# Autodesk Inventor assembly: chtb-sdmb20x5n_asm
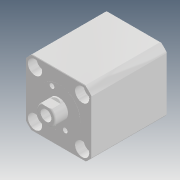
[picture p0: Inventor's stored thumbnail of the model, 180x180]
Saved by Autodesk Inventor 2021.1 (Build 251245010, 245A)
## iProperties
Company: Microsoft
Created: 2018-05
Part Number: chtb-sdmb20x5n_asm
Description: STEP AP214
Document SubType Name: Assembly
Designer: user
Title: chtb-sdmb20x5n_asm.STEP
Author: Windows
Revision Number: ÈÎºÎ
Sending System: SolidWorks 2015
Preprocessor: SwSTEP 2.0
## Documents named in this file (4)
- D:\Vault_2016\Projekty\Clamptek\Hydraulic\CHTB\CHTB-20\Inventor\CHTB-SDMB20x5N\chtb-sdmb20x5n_asm.iam
- D:\Vault_2016\Projekty\Clamptek\Hydraulic\CHTB\CHTB-20\Inventor\CHTB-SDMB20x5N\CHTB-SDMB20X5NBT.ipt
- D:\Vault_2016\Projekty\Clamptek\Hydraulic\CHTB\CHTB-20\Inventor\CHTB-SDMB20x5N\CHTB-SDMB20X5NHSG.ipt
- D:\Vault_2016\Projekty\Clamptek\Hydraulic\CHTB\CHTB-20\Inventor\CHTB-SDMB20x5N\QG_3.ipt
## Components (3 placed, 3 different names)
1. CHTB-SDMB20X5NBT_1
2. CHTB-SDMB20X5NHSG_2
3. QG_3_3
